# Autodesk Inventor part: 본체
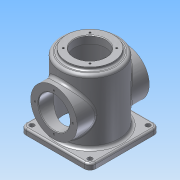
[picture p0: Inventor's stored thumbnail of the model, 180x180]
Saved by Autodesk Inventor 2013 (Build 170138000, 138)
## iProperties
Created: 2015-10
Part Number: 본체
Material: 알루미늄 6061
Document SubType Name: Modeling
Designer: Administrator
Density: 2.71 g/cm^3
Mass: 987.031 g
Surface Area: 1039.63 cm^2
Volume: 364.218 cm^3
Author: Administrator
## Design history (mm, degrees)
sketch "스케치1"
  geometry: L1 (-60, -50)-(60, -50); L2 (60, -50)-(60, -60); L3 (60, -60)-(-60, -60); L4 (-60, -60)-(-60, -50); 2 further points
  constraints: 8 end point, 2 parallel, 1 horizontal, 1 midpoint, 1 perpendicular, 1 vertical alignment
  dimensions: "d0" = 120 distance of L2.end L3.end; "d2" = 10 distance between parallel lines of L3 L1; "d3" = 60 distance from line of L3 point (0, 0)
extrude "돌출1" new body sketch "스케치1" stored distance "d4" = 120; taper "d5" = 0 deg
sketch "스케치2"
  geometry: C1 r 50 at (60, 60); 1 further point
  constraints: 1 centre point, 1 coincident
  dimensions: "d6" = 100 diameter of C1
extrude "돌출2" join sketch "스케치2" distance "d7" = 110; taper "d8" = 0 deg
sketch "스케치3"
  geometry: C1 r 50 at (0, 0) reference; C2 r 40 at (0, 0)
  constraints: 1 centre point, 1 coincident
  dimensions: "d9" = 80 diameter of C2
extrude "돌출3" join sketch "스케치3" distance "d10" = 5; taper "d11" = 0 deg
sketch "스케치5"
  geometry: C1 r 40 at (0, 0); 1 further point
  constraints: 1 centre point, 1 coincident
  dimensions: "d19" = 80 diameter of C1
extrude "돌출4" join sketch "스케치5" stored distance "d20" = 124; taper "d21" = 0 deg
sketch "스케치4"
  geometry: 2 further points
  constraints: 1 coincident
hole "구멍1" sketch "스케치4" at (60, -60) diameter "d12" = 54; stored, may be unused: countersink angle "d16" = 90 deg, drill point angle "d18" = 0 deg; dims "d13" = 6, "d14" = 90, "d15" = 112, "d17" = 125
hole "구멍2" diameter "d24" = 54; stored, may be unused: countersink angle "d28" = 90 deg, drill point angle "d30" = 0 deg; dims "d22" = 10, "d23" = 10, "d25" = 6, "d26" = 90, "d27" = 112, "d29" = 54
sketch "스케치6"
  geometry: C1 r 27 at (0, 0) reference; 1 further point
  constraints: 1 vertical alignment
  dimensions: "d31" = 32.5 distance of C1.centre point (0, 32.5)
hole "구멍3" sketch "스케치6" at (0, 32.5) diameter "d32" = 3.242; stored, may be unused: countersink angle "d36" = 90 deg, drill point angle "d38" = 118 deg; dims "d33" = 8, "d34" = 90, "d35" = 112, "d37" = 10
sketch "스케치7" dims "d43" = 65
  geometry: L1 (0, 0)-(0, 40); L2 (0, 0)-(22.981, 22.981); 2 further points
  constraints: 4 end point, 2 coincident, 1 vertical, 1 vertical alignment, 4 other
  dimensions: "d42" = 45 deg angle of L2 L1
hole "구멍4" sketch "스케치7" at (22.981, 22.981) diameter "d44" = 3.242; stored, may be unused: countersink angle "d48" = 90 deg, drill point angle "d50" = 118 deg; dims "d45" = 8, "d46" = 90, "d47" = 112, "d49" = 10
sketch "스케치8"
  geometry: C1 r 50 at (60, 60) reference; 2 further points
  constraints: 1 horizontal alignment
  dimensions: "d54" = 100 distance of point (110, 110) point (10, 110); "d56" = 50 horizontal distance of C1.centre point (10, 110); "d57" = 50 horizontal distance of C1.centre point (10, 110)
hole "구멍5" sketch "스케치8" at (10, 110), (110, 110) diameter "d58" = 8; stored, may be unused: countersink angle "d62" = 90 deg, drill point angle "d64" = 118 deg; dims "d59" = 8, "d60" = 90, "d61" = 112, "d63" = 10
node "작업 평면1"
sketch "스케치9"
  geometry: L1 (60, 60)-(60, -60) reference; 2 further points
  constraints: 1 horizontal alignment, 1 other
  dimensions: "d66" = 70 distance from line of point (-10, 0) L1
feature "엠보싱1" sketch "스케치9" dims "d0" = 120, "d2" = 10, "d3" = 60, "d67" = 0.5, "d68" = 0
fillet "모깎기1" dims "d69" = 10
chamfer "모따기1" distance "d70" = 3; stored, may be unused: second distance "d71" = 2, angle "d72" = 45 deg
fillet "모깎기2" dims "d73" = 3
fillet "모깎기3" dims "d74" = 5
chamfer "모따기2" distance "d75" = 1; stored, may be unused: second distance "d76" = 2, angle "d77" = 45 deg
chamfer "모따기3" distance "d78" = 1; stored, may be unused: second distance "d79" = 2, angle "d80" = 45 deg
fillet "모깎기4" dims "d81" = 5
fillet "모깎기5" dims "d82" = 3
fillet "모깎기6" dims "d83" = 3
node "솔리드1"
pattern_circular "원형 패턴1" dims angle "d40" = 360 deg
mirror "대칭1"
pattern_circular "원형 패턴2" dims angle "d52" = 360 deg
mirror "대칭2"
